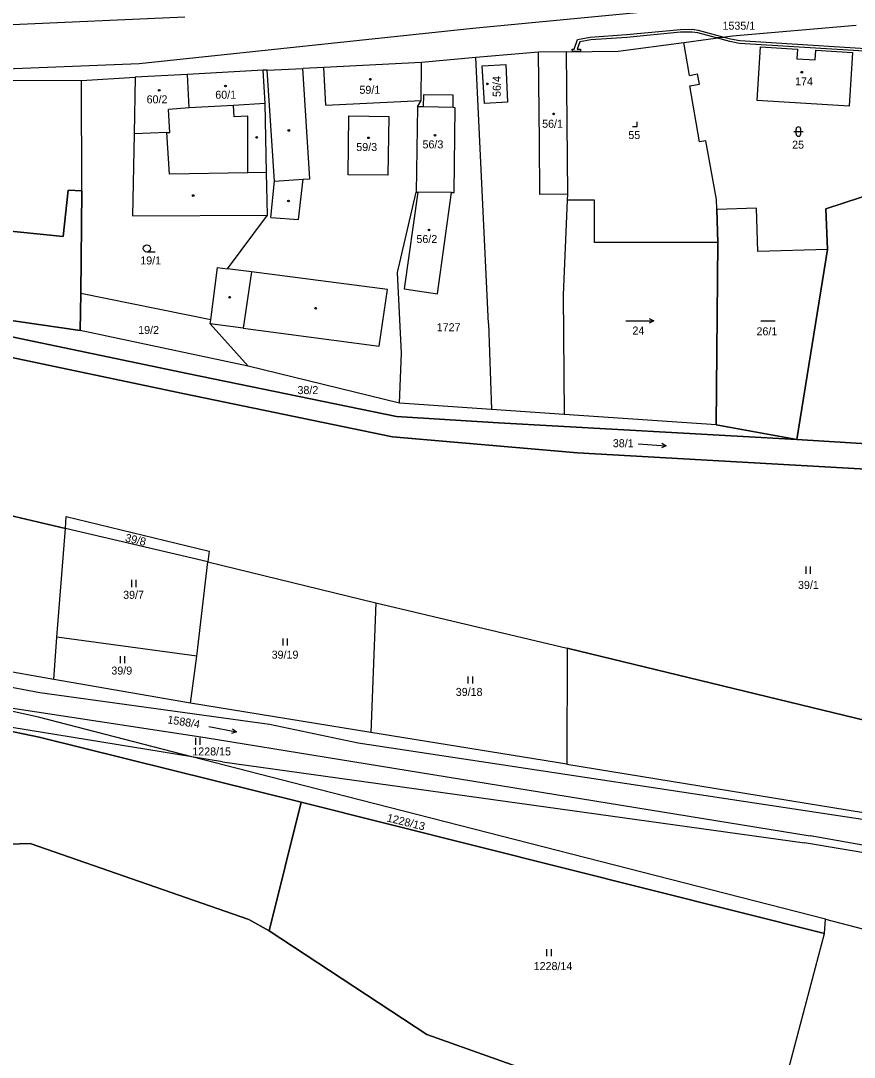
# Model space of a CAD drawing. Extents: x -801826 to -800592, y -1032871 to -1031813.
# Drawn here: x -801458.2 to -801281.1, y -1032516 to -1032295.9 of the extents above; entities that cross this region are included whole.
import ezdxf

# ---------------------------------------------------------------- set-up
doc = ezdxf.new("R2010")
doc.units = 0
for name, color, linetype in [('Vrstva 1', 7, 'Continuous'), ('Vrstva 18', 7, 'Continuous'), ('Vrstva 19', 7, 'Continuous'), ('Vrstva 25', 7, 'Continuous'), ('Vrstva 27', 7, 'Continuous'), ('Vrstva 4', 7, 'Continuous')]:
    doc.layers.add(name, color=color, linetype=linetype)

msp = doc.modelspace()

# ---------------------------------------------------------------- linework, layer by layer
at = {"layer": 'Vrstva 1'}
for p, q in [((-801362.11, -1032297.43), (-801305.07, -1032292.01)), ((-801466.62, -1032296.97), (-801423.3, -1032295.08)), ((-801432.98, -1032305), (-801362.11, -1032297.43)), ((-801306.97, -1032299.09), (-801280.76, -1032296.82)), ((-801317.32, -1032300.49), (-801306.97, -1032299.09)), ((-801342.33, -1032302.49), (-801331.24, -1032302.38)), ((-801331.24, -1032302.38), (-801317.32, -1032300.49)), ((-801316.13, -1032307.48), (-801317.32, -1032300.49)), ((-801301.73, -1032312.84), (-801301.01, -1032301.41)), ((-801301.01, -1032301.41), (-801293.19, -1032301.91)), ((-801293.19, -1032301.91), (-801293.33, -1032303.98)), ((-801289.43, -1032304.21), (-801289.3, -1032302.16)), ((-801289.3, -1032302.16), (-801281.5, -1032302.65)), ((-801361.49, -1032303.72), (-801373.06, -1032304.73)), ((-801348.18, -1032302.55), (-801361.49, -1032303.72)), ((-801358.8, -1032360.19), (-801361.49, -1032303.72)), ((-801342.33, -1032302.49), (-801348.18, -1032302.55)), ((-801342.33, -1032302.49), (-801342.03, -1032332.74)), ((-801293.33, -1032303.98), (-801289.43, -1032304.21)), ((-801281.5, -1032302.65), (-801282.24, -1032314.05)), ((-801471.17, -1032306.51), (-801432.98, -1032305)), ((-801406.64, -1032306.4), (-801422.77, -1032307.27)), ((-801405.84, -1032306.36), (-801406.64, -1032306.4)), ((-801406.26, -1032313.49), (-801406.64, -1032306.4)), ((-801405.84, -1032306.36), (-801398.24, -1032306.02)), ((-801393.8, -1032305.8), (-801398.24, -1032306.02)), ((-801373.06, -1032304.73), (-801393.8, -1032305.8)), ((-801373.09, -1032312.85), (-801373.06, -1032304.73)), ((-801360.13, -1032305.49), (-801355.11, -1032305.18)), ((-801359.64, -1032313.49), (-801360.13, -1032305.49)), ((-801355.11, -1032305.18), (-801354.77, -1032313.2)), ((-801473.65, -1032308.44), (-801445.24, -1032308.56)), ((-801445.24, -1032308.56), (-801433.85, -1032307.87)), ((-801445.2, -1032332.02), (-801445.24, -1032308.56)), ((-801433.85, -1032307.87), (-801434.08, -1032319.87)), ((-801422.77, -1032307.27), (-801433.85, -1032307.87)), ((-801422.38, -1032314.36), (-801422.77, -1032307.27)), ((-801316.13, -1032307.48), (-801314.39, -1032307.18)), ((-801314.02, -1032309.35), (-801314.39, -1032307.18)), ((-801316.03, -1032309.69), (-801314.02, -1032309.35)), ((-801313.99, -1032321.63), (-801316.03, -1032309.69)), ((-801373.91, -1032314.18), (-801373.09, -1032312.85)), ((-801372.64, -1032311.6), (-801372.69, -1032314.2)), ((-801366.31, -1032311.68), (-801372.64, -1032311.6)), ((-801366.34, -1032314.34), (-801366.31, -1032311.68)), ((-801354.77, -1032313.2), (-801359.64, -1032313.49)), ((-801282.24, -1032314.05), (-801301.73, -1032312.84)), ((-801422.38, -1032314.36), (-801426.77, -1032314.7)), ((-801426.47, -1032319.59), (-801426.77, -1032314.7)), ((-801405.95, -1032328.09), (-801406.26, -1032313.49)), ((-801373.91, -1032314.18), (-801374.15, -1032332.27)), ((-801372.69, -1032314.2), (-801373.91, -1032314.18)), ((-801365.88, -1032314.35), (-801366.34, -1032314.34)), ((-801366.08, -1032332.38), (-801365.88, -1032314.35)), ((-801388.64, -1032328.58), (-801388.47, -1032316.1)), ((-801388.47, -1032316.1), (-801379.99, -1032316.22)), ((-801379.99, -1032316.22), (-801380.17, -1032328.67)), ((-801434.08, -1032319.87), (-801434.41, -1032337.28)), ((-801427.1, -1032319.63), (-801434.08, -1032319.87)), ((-801427.1, -1032319.63), (-801426.47, -1032319.59)), ((-801312.69, -1032321.38), (-801313.99, -1032321.63)), ((-801310.41, -1032333.85), (-801312.69, -1032321.38)), ((-801405.76, -1032337.19), (-801405.95, -1032328.09)), ((-801380.17, -1032328.67), (-801388.64, -1032328.58)), ((-801287.15, -1032335.8), (-801268.74, -1032329.75)), ((-801268.74, -1032329.75), (-801287.15, -1032335.8)), ((-801449.11, -1032341.7), (-801448.06, -1032331.85)), ((-801448.06, -1032331.85), (-801449.11, -1032341.7)), ((-801448.06, -1032331.85), (-801445.2, -1032332.02)), ((-801445.2, -1032332.02), (-801448.06, -1032331.85)), ((-801445.2, -1032332.02), (-801445.38, -1032353.82)), ((-801445.38, -1032353.82), (-801445.2, -1032332.02)), ((-801378.15, -1032349.33), (-801374.15, -1032332.27)), ((-801373.8, -1032332.27), (-801376.73, -1032352.85)), ((-801374.15, -1032332.27), (-801373.8, -1032332.27)), ((-801366.67, -1032332.38), (-801373.8, -1032332.27)), ((-801369.66, -1032353.87), (-801366.67, -1032332.38)), ((-801366.67, -1032332.38), (-801366.08, -1032332.38)), ((-801342.03, -1032332.74), (-801342.09, -1032334)), ((-801342.09, -1032334), (-801342.98, -1032354.12)), ((-801336.3, -1032334), (-801342.09, -1032334)), ((-801336.3, -1032342.99), (-801336.3, -1032334)), ((-801310.33, -1032335.95), (-801310.41, -1032333.85)), ((-801434.41, -1032337.28), (-801405.76, -1032337.19)), ((-801414.25, -1032348.59), (-801405.76, -1032337.19)), ((-801301.89, -1032335.67), (-801310.33, -1032335.95)), ((-801301.89, -1032335.67), (-801310.33, -1032335.95)), ((-801310.08, -1032343), (-801310.33, -1032335.95)), ((-801310.33, -1032335.95), (-801310.08, -1032343)), ((-801301.59, -1032344.91), (-801301.89, -1032335.67)), ((-801301.59, -1032344.91), (-801301.89, -1032335.67)), ((-801286.8, -1032344.43), (-801287.15, -1032335.8)), ((-801287.15, -1032335.8), (-801286.8, -1032344.43)), ((-801476.52, -1032339), (-801449.11, -1032341.7)), ((-801449.11, -1032341.7), (-801476.52, -1032339)), ((-801310.08, -1032343), (-801336.3, -1032342.99)), ((-801310.45, -1032381.72), (-801310.08, -1032343)), ((-801310.08, -1032343), (-801310.45, -1032381.72)), ((-801286.8, -1032344.43), (-801301.59, -1032344.91)), ((-801286.8, -1032344.43), (-801301.59, -1032344.91)), ((-801293.31, -1032384.79), (-801286.8, -1032344.43)), ((-801293.31, -1032384.79), (-801286.8, -1032344.43)), ((-801286.8, -1032344.43), (-801293.31, -1032384.79)), ((-801417.8, -1032359.43), (-801416.38, -1032348.31)), ((-801416.38, -1032348.31), (-801414.25, -1032348.59)), ((-801377.29, -1032366.51), (-801378.15, -1032349.33)), ((-801376.73, -1032352.85), (-801369.66, -1032353.87)), ((-801445.38, -1032353.82), (-801445.51, -1032361.66)), ((-801445.51, -1032361.66), (-801445.38, -1032353.82)), ((-801417.8, -1032359.43), (-801445.38, -1032353.82)), ((-801342.98, -1032354.12), (-801342.75, -1032379.48)), ((-801445.51, -1032361.66), (-801478.84, -1032356.78)), ((-801478.84, -1032356.78), (-801445.51, -1032361.66)), ((-801445.51, -1032361.66), (-801478.84, -1032356.78)), ((-801486.13, -1032357.6), (-801422.46, -1032370.88)), ((-801422.46, -1032370.88), (-801486.13, -1032357.6)), ((-801486.13, -1032357.6), (-801422.46, -1032370.88)), ((-801417.9, -1032360.23), (-801417.8, -1032359.43)), ((-801409.86, -1032369.27), (-801445.51, -1032361.66)), ((-801409.86, -1032369.27), (-801445.51, -1032361.66)), ((-801409.86, -1032369.27), (-801417.9, -1032360.23)), ((-801358.8, -1032360.19), (-801358.16, -1032378.41)), ((-801423.35, -1032375.12), (-801479.83, -1032363.24)), ((-801479.83, -1032363.24), (-801423.35, -1032375.12)), ((-801423.35, -1032375.12), (-801479.83, -1032363.24)), ((-801377.71, -1032377.06), (-801377.29, -1032366.51)), ((-801377.71, -1032377.06), (-801409.86, -1032369.27)), ((-801377.71, -1032377.06), (-801409.86, -1032369.27)), ((-801422.46, -1032370.88), (-801378.36, -1032379.9)), ((-801378.36, -1032379.9), (-801422.46, -1032370.88)), ((-801422.46, -1032370.88), (-801378.36, -1032379.9)), ((-801379.17, -1032384.27), (-801423.35, -1032375.12)), ((-801423.35, -1032375.12), (-801379.17, -1032384.27)), ((-801379.17, -1032384.27), (-801423.35, -1032375.12)), ((-801358.16, -1032378.41), (-801377.71, -1032377.06)), ((-801358.16, -1032378.41), (-801377.71, -1032377.06)), ((-801342.75, -1032379.48), (-801358.16, -1032378.41)), ((-801342.75, -1032379.48), (-801358.16, -1032378.41)), ((-801378.36, -1032379.9), (-801356.68, -1032381.25)), ((-801356.68, -1032381.25), (-801378.36, -1032379.9)), ((-801378.36, -1032379.9), (-801356.68, -1032381.25)), ((-801356.68, -1032381.25), (-801293.31, -1032384.79)), ((-801293.31, -1032384.79), (-801356.68, -1032381.25)), ((-801356.68, -1032381.25), (-801293.31, -1032384.79)), ((-801310.45, -1032381.72), (-801342.75, -1032379.48)), ((-801310.45, -1032381.72), (-801342.75, -1032379.48)), ((-801293.31, -1032384.79), (-801310.45, -1032381.72)), ((-801310.45, -1032381.72), (-801293.31, -1032384.79)), ((-801293.31, -1032384.79), (-801310.45, -1032381.72)), ((-801339.88, -1032387.67), (-801379.17, -1032384.27)), ((-801379.17, -1032384.27), (-801339.88, -1032387.67)), ((-801339.88, -1032387.67), (-801379.17, -1032384.27)), ((-801293.31, -1032384.79), (-801263.9, -1032386.64)), ((-801293.31, -1032384.79), (-801263.9, -1032386.64)), ((-801263.9, -1032386.64), (-801293.31, -1032384.79)), ((-801227.68, -1032394.03), (-801339.88, -1032387.67)), ((-801339.88, -1032387.67), (-801227.68, -1032394.03)), ((-801227.68, -1032394.03), (-801339.88, -1032387.67)), ((-801448.68, -1032403.68), (-801512.18, -1032388.72)), ((-801512.18, -1032388.72), (-801448.68, -1032403.68)), ((-801448.68, -1032403.68), (-801448.48, -1032401.14)), ((-801448.68, -1032403.68), (-801448.48, -1032401.14)), ((-801448.48, -1032401.14), (-801418.14, -1032408.5)), ((-801448.48, -1032401.14), (-801418.14, -1032408.5)), ((-801450.46, -1032426.78), (-801448.68, -1032403.68)), ((-801418.41, -1032410.81), (-801448.68, -1032403.68)), ((-801418.14, -1032408.5), (-801418.41, -1032410.81)), ((-801418.14, -1032408.5), (-801418.41, -1032410.81)), ((-801420.75, -1032430.8), (-801418.41, -1032410.81)), ((-801418.41, -1032410.81), (-801382.77, -1032419.46)), ((-801418.41, -1032410.81), (-801382.77, -1032419.46)), ((-801451.09, -1032435.8), (-801551.54, -1032417.61)), ((-801551.9, -1032420.25), (-801454.13, -1032438.52)), ((-801382.77, -1032419.46), (-801383.8, -1032447.01)), ((-801382.77, -1032419.46), (-801342.09, -1032429.1)), ((-801382.77, -1032419.46), (-801342.09, -1032429.1)), ((-801451.09, -1032435.8), (-801450.46, -1032426.78)), ((-801420.75, -1032430.8), (-801450.46, -1032426.78)), ((-801342.09, -1032429.1), (-801342.15, -1032453.77)), ((-801217.1, -1032459.5), (-801342.09, -1032429.1)), ((-801342.09, -1032429.1), (-801217.1, -1032459.5)), ((-801422.12, -1032440.78), (-801420.75, -1032430.8)), ((-801422.12, -1032440.78), (-801451.09, -1032435.8)), ((-801454.13, -1032438.52), (-801405.3, -1032445.23)), ((-801454.37, -1032443.75), (-801472.22, -1032439.95)), ((-801472.22, -1032439.95), (-801418.97, -1032448.1)), ((-801383.8, -1032447.01), (-801422.12, -1032440.78)), ((-801421.82, -1032452.17), (-801478.34, -1032443.01)), ((-801478.34, -1032443.01), (-801454.22, -1032448.05)), ((-801454.22, -1032448.05), (-801478.34, -1032443.01)), ((-801421.82, -1032452.17), (-801454.37, -1032443.75)), ((-801405.3, -1032445.23), (-801386.46, -1032449.23)), ((-801342.15, -1032453.77), (-801383.8, -1032447.01)), ((-801454.22, -1032448.05), (-801398.63, -1032461.84)), ((-801398.63, -1032461.84), (-801454.22, -1032448.05)), ((-801418.97, -1032448.1), (-801290.52, -1032469)), ((-801386.46, -1032449.23), (-801268.54, -1032467.11)), ((-801397.91, -1032458.35), (-801421.82, -1032452.17)), ((-801415.32, -1032453.22), (-801421.82, -1032452.17)), ((-801415.32, -1032453.22), (-801291.7, -1032470.46)), ((-801342.15, -1032453.77), (-801097.8, -1032493.48)), ((-801287.22, -1032486.69), (-801397.91, -1032458.35)), ((-801405.39, -1032489.16), (-801398.63, -1032461.84)), ((-801405.39, -1032489.16), (-801398.63, -1032461.84)), ((-801398.63, -1032461.84), (-801405.39, -1032489.16)), ((-801398.63, -1032461.84), (-801287.44, -1032489.71)), ((-801287.44, -1032489.71), (-801398.63, -1032461.84)), ((-801105.37, -1032501.75), (-801290.52, -1032469)), ((-801479.37, -1032471.31), (-801456.14, -1032470.6)), ((-801479.37, -1032471.31), (-801456.14, -1032470.6)), ((-801456.14, -1032470.6), (-801479.37, -1032471.31)), ((-801456.14, -1032470.6), (-801409.68, -1032486.76)), ((-801456.14, -1032470.6), (-801409.68, -1032486.76)), ((-801409.68, -1032486.76), (-801456.14, -1032470.6)), ((-801144.19, -1032495.42), (-801291.7, -1032470.46)), ((-801409.68, -1032486.76), (-801405.39, -1032489.16)), ((-801409.68, -1032486.76), (-801405.39, -1032489.16)), ((-801405.39, -1032489.16), (-801409.68, -1032486.76)), ((-801287.44, -1032489.71), (-801287.22, -1032486.69)), ((-801287.22, -1032486.69), (-801056.37, -1032546.95)), ((-801405.39, -1032489.16), (-801371.9, -1032511.12)), ((-801405.39, -1032489.16), (-801371.9, -1032511.12)), ((-801371.9, -1032511.12), (-801405.39, -1032489.16)), ((-801299.36, -1032534.57), (-801287.44, -1032489.71)), ((-801299.36, -1032534.57), (-801287.44, -1032489.71)), ((-801371.9, -1032511.12), (-801316.85, -1032530.71)), ((-801371.9, -1032511.12), (-801316.85, -1032530.71)), ((-801316.85, -1032530.71), (-801371.9, -1032511.12))]:
    msp.add_line(p, q, dxfattribs=at)
at = {"layer": 'Vrstva 25'}
for p, q in [((-801327.25, -1032318.36), (-801327.25, -1032317.36)), ((-801328.25, -1032318.36), (-801327.25, -1032318.36)), ((-801294, -1032319.42), (-801292, -1032319.42)), ((-801293.5, -1032319.92), (-801293.5, -1032318.92)), ((-801292.5, -1032319.92), (-801292.5, -1032318.92)), ((-801429.62, -1032345), (-801431.37, -1032345)), ((-801329.67, -1032359.59), (-801323.67, -1032359.59)), ((-801300.95, -1032359.63), (-801297.95, -1032359.63)), ((-801327.03, -1032385.71), (-801321.05, -1032386.15)), ((-801291.42, -1032411.8), (-801291.42, -1032413.3)), ((-801290.4, -1032413.3), (-801290.4, -1032411.8)), ((-801434.66, -1032414.64), (-801434.66, -1032416.14)), ((-801433.64, -1032416.14), (-801433.64, -1032414.64)), ((-801402.52, -1032427.05), (-801402.52, -1032428.55)), ((-801401.49, -1032428.55), (-801401.49, -1032427.05)), ((-801437.06, -1032430.79), (-801437.06, -1032432.29)), ((-801436.04, -1032432.29), (-801436.04, -1032430.79)), ((-801363.19, -1032435.1), (-801363.19, -1032436.6)), ((-801362.17, -1032436.6), (-801362.17, -1032435.1)), ((-801418.2, -1032445.74), (-801412.32, -1032446.92)), ((-801421.06, -1032448.14), (-801421.06, -1032449.64)), ((-801420.04, -1032449.64), (-801420.04, -1032448.14)), ((-801346.48, -1032493.04), (-801346.48, -1032494.54)), ((-801345.46, -1032494.54), (-801345.46, -1032493.04))]:
    msp.add_line(p, q, dxfattribs=at)
for points in [[(-801324.67, -1032359.09), (-801323.67, -1032359.59), (-801324.67, -1032360.09)], [(-801322.01, -1032385.58), (-801321.05, -1032386.15), (-801322.08, -1032386.57)], [(-801413.2, -1032446.23), (-801412.32, -1032446.92), (-801413.4, -1032447.21)]]:
    msp.add_lwpolyline(points, dxfattribs=at)
for centre, radius in [((-801292.28, -1032306.81), 0.175), ((-801383.9, -1032308.3), 0.175), ((-801428.75, -1032310.67), 0.175), ((-801414.67, -1032309.74), 0.175), ((-801359.07, -1032309.3), 0.175), ((-801344.96, -1032315.66), 0.175), ((-801401.22, -1032319.18), 0.175), ((-801408.06, -1032320.67), 0.175), ((-801384.28, -1032320.75), 0.175), ((-801370.18, -1032320.19), 0.175), ((-801421.53, -1032333), 0.175), ((-801401.29, -1032334.15), 0.175), ((-801371.44, -1032340.32), 0.175), ((-801431.37, -1032344.25), 0.75), ((-801413.78, -1032354.6), 0.175), ((-801395.51, -1032356.93), 0.175)]:
    msp.add_circle(centre, radius, dxfattribs=at)
for centre, start, end in [((-801293, -1032318.92), 0, 180), ((-801293, -1032319.92), 180, 0)]:
    msp.add_arc(centre, 0.5, start, end, dxfattribs=at)
at = {"layer": 'Vrstva 27'}
for points in [[(-801310.37, -1032299.55), (-801314.38, -1032298.45), (-801315.59, -1032298.3), (-801318.02, -1032298.33), (-801329.43, -1032299.44), (-801337.11, -1032299.94), (-801339.43, -1032300.38), (-801339.97, -1032301.92), (-801339.3, -1032301.9), (-801339.26, -1032302.4), (-801340.99, -1032302.42), (-801341.04, -1032301.95), (-801340.61, -1032301.94), (-801339.89, -1032299.86), (-801337.19, -1032299.34), (-801329.47, -1032298.84), (-801318.06, -1032297.73), (-801315.55, -1032297.7), (-801314.26, -1032297.87), (-801308.86, -1032299.35), (-801310.37, -1032299.55)], [(-801307.45, -1032299.73), (-801305.46, -1032300.11), (-801269.81, -1032302.33), (-801269.72, -1032302.93), (-801305.54, -1032300.71), (-801307.59, -1032300.31), (-801310.37, -1032299.55), (-801308.86, -1032299.35), (-801307.45, -1032299.73)]]:
    msp.add_lwpolyline(points, dxfattribs=at)
at = {"layer": 'Vrstva 4'}
for p, q in [((-801347.99, -1032321.61), (-801348.18, -1032302.55)), ((-801404.29, -1032329.92), (-801405.84, -1032306.36)), ((-801396.78, -1032329.45), (-801398.24, -1032306.02)), ((-801393.37, -1032313.83), (-801393.8, -1032305.8)), ((-801393.37, -1032313.83), (-801373.09, -1032312.85)), ((-801412.98, -1032313.85), (-801422.38, -1032314.36)), ((-801406.26, -1032313.49), (-801412.98, -1032313.85)), ((-801412.84, -1032316.3), (-801412.98, -1032313.85)), ((-801366.34, -1032314.34), (-801372.69, -1032314.2)), ((-801409.95, -1032316.14), (-801412.84, -1032316.3)), ((-801409.95, -1032328.17), (-801409.95, -1032316.14)), ((-801426.56, -1032328.47), (-801427.1, -1032319.63)), ((-801347.88, -1032332.8), (-801347.99, -1032321.61)), ((-801409.95, -1032328.17), (-801426.56, -1032328.47)), ((-801405.95, -1032328.09), (-801409.95, -1032328.17)), ((-801405.02, -1032337.65), (-801404.29, -1032329.92)), ((-801404.29, -1032329.92), (-801398.18, -1032329.54)), ((-801399.14, -1032338.09), (-801398.18, -1032329.54)), ((-801398.18, -1032329.54), (-801396.78, -1032329.45)), ((-801342.03, -1032332.74), (-801347.88, -1032332.8)), ((-801405.02, -1032337.65), (-801399.14, -1032338.09)), ((-801409.13, -1032349.24), (-801414.25, -1032348.59)), ((-801409.13, -1032349.24), (-801410.94, -1032361.15)), ((-801380.23, -1032352.94), (-801409.13, -1032349.24)), ((-801382.02, -1032364.96), (-801380.23, -1032352.94)), ((-801410.94, -1032361.15), (-801417.9, -1032360.23)), ((-801410.94, -1032361.15), (-801382.02, -1032364.96))]:
    msp.add_line(p, q, dxfattribs=at)

# ---------------------------------------------------------------- texts
at = {"layer": 'Vrstva 18'}
for s, p in [('1535/1', (-801309.12, -1032297.79)), ('25', (-801294.33, -1032323.05)), ('19/1', (-801432.77, -1032347.64)), ('19/2', (-801433.21, -1032362.4)), ('1727', (-801369.81, -1032361.82)), ('24', (-801328.24, -1032362.52)), ('26/1', (-801301.9, -1032362.69)), ('38/2', (-801399.38, -1032375.17)), ('38/1', (-801332.41, -1032386.45)), ('39/7', (-801436.41, -1032418.64)), ('39/1', (-801293.09, -1032416.54)), ('39/19', (-801404.87, -1032431.35)), ('39/9', (-801438.91, -1032434.73)), ('39/18', (-801365.77, -1032439.26)), ('1228/15', (-801421.72, -1032451.9)), ('1228/14', (-801349.22, -1032497.48))]:
    msp.add_text(s, height=1.7, dxfattribs=at).set_placement(p)
for s, rotation, p in [('39/8', 347.2362, (-801436.09, -1032406.44)), ('1588/4', 351.0116, (-801427.09, -1032445.06)), ('1228/13', 346.1515, (-801380.52, -1032465.88))]:
    msp.add_text(s, height=1.7, rotation=rotation, dxfattribs=at).set_placement(p)
at = {"layer": 'Vrstva 19'}
msp.add_text('56/4', height=1.7, rotation=90, dxfattribs=at).set_placement((-801356.21, -1032312.07))
for s, p in [('174', (-801293.7, -1032309.61)), ('60/1', (-801416.84, -1032312.45)), ('59/1', (-801386.22, -1032311.4)), ('60/2', (-801431.42, -1032313.43)), ('56/1', (-801347.42, -1032318.61)), ('55', (-801329.11, -1032321.01)), ('59/3', (-801386.89, -1032323.55)), ('56/3', (-801372.83, -1032322.99)), ('56/2', (-801374.12, -1032343.09))]:
    msp.add_text(s, height=1.7, dxfattribs=at).set_placement(p)

doc.saveas('drawing.dxf')
